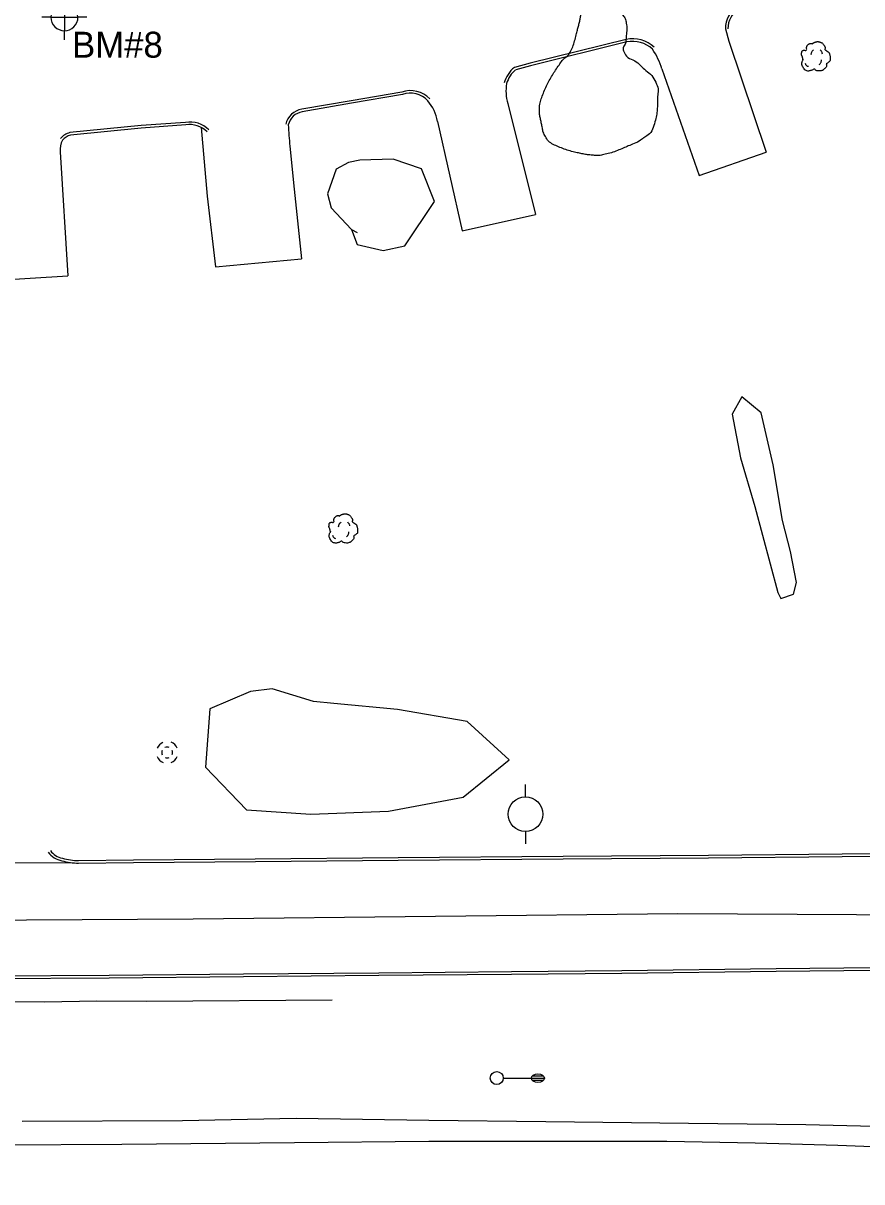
# Model space of a CAD drawing. Extents: x 2145380 to 2156929, y 139568 to 149130.
# Drawn here: x 2148643.4 to 2148837.2, y 143121.1 to 143388.8 of the extents above; entities that cross this region are included whole.
import ezdxf

# ---------------------------------------------------------------- set-up
doc = ezdxf.new("R2010")
doc.units = 0
for name, color, linetype in [('SURV_Benchmark', 7, 'Continuous'), ('SURV_Text', 7, 'Continuous'), ('TOPO_Asphalt', 7, 'Continuous'), ('TOPO_Curb Back', 7, 'Continuous'), ('TOPO_DRAIN_Manhole', 7, 'Continuous'), ('TOPO_Flowline', 7, 'Continuous'), ('TOPO_Light Pole', 7, 'Continuous'), ('TOPO_Power Pole', 7, 'Continuous'), ('TOPO_Tree', 7, 'Continuous'), ('TOPO_Tree Line', 7, 'Continuous')]:
    doc.layers.add(name, color=color, linetype=linetype)

# ---------------------------------------------------------------- blocks, each defined once
blk = doc.blocks.new('MHEXST')
at = {"layer": 'TOPO_DRAIN_Manhole'}
for centre, radius, start, end in [((-0.1, 0.3), 12.7, 112.9748, 158.2636), ((-0.1, 0.1), 6.35, 157.9722, 204.161), ((-0.1, 0.1), 6.35, 66.1941, 113.691), ((-0.1, 0.3), 12.7, 22.0744, 68.6991), ((-0.1, 0.1), 6.35, 336.8023, 21.4046), ((-0.1, 0.3), 12.7, 202.6921, 248.1938), ((-0.1, 0.1), 6.35, 248.5791, 293.1995), ((-0.1, 0.3), 12.7, 291.7963, 337.3032)]:
    blk.add_arc(centre, radius, start, end, dxfattribs=at)
blk = doc.blocks.new('LP')
at = {"layer": 'TOPO_Light Pole'}
blk.add_line((3.81, 0), (20.32, 0), dxfattribs=at)
for points in [[(20.32, 0), (27.94, 0)], [(20.32, 0), (23.5, 0)], [(20.83, 1.27), (27.43, 1.27)], [(20.83, 1.27), (23.5, 1.27)], [(23.71, 1.27), (27.43, 1.27)], [(23.71, 0), (27.94, 0)], [(20.83, -1.27), (27.43, -1.27)], [(20.83, -1.27), (23.5, -1.27)], [(23.71, -1.27), (27.43, -1.27)]]:
    blk.add_lwpolyline(points, dxfattribs=at)
blk.add_circle((0, 0), 3.81, dxfattribs=at)
blk.add_ellipse((24.13, 0), major_axis=(3.81, 0), ratio=0.666667, dxfattribs=at)
blk = doc.blocks.new('TREE')
at = {"layer": 'TOPO_Tree'}
for points in [[(-14.1, -0.4), (-14.2, 0.5), (-14.4, 1.4), (-14.6, 2.3), (-14.8, 3.2), (-15.5, 4), (-15.7, 4.9), (-15.8, 5.6), (-15.7, 6.3), (-15.7, 7), (-15.6, 7.9), (-15.7, 8.8), (-15.1, 9.7), (-14.6, 10.4), (-13.8, 10.5), (-13, 10.7), (-12.2, 11), (-11.1, 10), (-10.4, 10.7), (-9.4, 11.7), (-10.3, 13.3), (-9.8, 14.4), (-9.6, 15.1), (-9.3, 15.9), (-8.8, 16.5), (-8.2, 17.3), (-7.5, 17.7), (-6.7, 18.1), (-6.1, 18.4), (-5.6, 18.6), (-5.1, 18.7), (-4.5, 18.7), (-4, 18.5), (-3.5, 18.1)], [(-3.5, 17.6), (-3.1, 18.3), (-2.6, 18.8), (-1.9, 19.2), (-1, 19.7), (-0.2, 20), (0.7, 20.2), (1.6, 20.5), (2.5, 20.8), (3.4, 20.8), (4.1, 20.7), (4.8, 20.5), (5.5, 20.2), (6.4, 19.9), (7.3, 19.7), (8.2, 19.2), (9.4, 18.4), (10, 17.2), (10.8, 16), (11.2, 15.3), (11.6, 14.6), (11.9, 13.9), (12.2, 13.1), (11.4, 12), (11.9, 11.2), (12, 11), (12.2, 10.9), (12.4, 10.7), (12.9, 10.4), (13.5, 10), (14, 9.7), (14.7, 9.2), (15.4, 8.7), (16.1, 8.1), (16.7, 7.5), (16.9, 6.7), (17.1, 6), (17.6, 4.4), (17.7, 2.8), (17.7, 1.2), (17.7, -0.2), (17.8, -2.2), (16.6, -3), (15.5, -3.8), (14.3, -4.6), (13.2, -5.3)], [(13.2, -5.3), (13.3, -5.8), (13.4, -6.3), (13.4, -6.7), (13.8, -8.5), (12.2, -10), (10.8, -11.5), (10, -12.3), (9.1, -12.8), (8.2, -13.1), (6, -13.8), (3.3, -13.6), (1.3, -13.1), (0.5, -12.9), (-0.1, -11.4), (-0.8, -11.5), (-2, -11.6), (-3.3, -12.8), (-4.5, -13.1), (-6.1, -13.5), (-7.8, -14), (-9.3, -13.6), (-11.4, -13.1), (-12.8, -11.4), (-14.1, -9.4), (-15.3, -7.3), (-15.6, -5.1), (-15.1, -3), (-14.9, -1.9), (-13.9, -0.8), (-13.5, 0.1)], [(-4.2, 5.1), (-4.5, 6.1), (-4.3, 7.2), (-3.8, 8.2), (-3.3, 9.3), (-2.7, 10.3), (-1.6, 11)], [(5.9, 11.2), (6.5, 10.7), (7, 10.2), (7.4, 9.5), (7.9, 8.6), (8.3, 7.6), (8.5, 6.6)], [(-11.4, -4.5), (-11.5, -5.4), (-11, -6.3), (-10.1, -7.2), (-9.3, -8), (-8.5, -8.3), (-7.7, -8.1)], [(4.8, -6.3), (5.7, -5.7), (6.3, -4.9), (6.8, -3.9), (7.4, -2.8), (7.6, -1.7), (7.5, -0.6)]]:
    blk.add_open_spline(points, degree=3, dxfattribs=at)
blk = doc.blocks.new('POWPOL')
at = {"layer": 'TOPO_Power Pole'}
for p, q in [((0, 10.16), (0, 17.34)), ((0, -10.16), (0, -17.34))]:
    blk.add_line(p, q, dxfattribs=at)
blk.add_circle((0, 0), 10.16, dxfattribs=at)
blk = doc.blocks.new('BM')
at = {"layer": 'SURV_Benchmark'}
for p, q in [((0, 2.49), (0, 4.15)), ((-2.49, 0), (-4.16, 0)), ((4.16, 0), (2.49, 0)), ((0, -4.16), (0, -2.49))]:
    blk.add_line(p, q, dxfattribs=at)
for points in [[(0, 2.49), (0, 2.49), (0, 0), (2.49, 0), (2.49, 0), (2.49, 0)], [(0, 2.49), (0, 2.49), (0, 0), (2.49, 0), (2.49, 0), (2.49, 0), (2.49, 0)], [(-2.5, 0), (-2.49, 0), (0, 0), (0, -2.49), (0, -2.49)], [(-2.5, 0), (-2.49, 0), (0, 0), (0, -2.49), (0, -2.49)]]:
    blk.add_lwpolyline(points, dxfattribs=at)
for start, end in [(90.0638, 180.0068), (0.0638, 90.0068), (0.0638, 90.0068), (180.0638, 270.0068), (180.0638, 270.0068), (269.9472, 359.9927)]:
    blk.add_arc((0, 0), 2.5, start, end, dxfattribs=at)

msp = doc.modelspace()

# ---------------------------------------------------------------- linework, layer by layer
at = {"layer": 'TOPO_Asphalt'}
msp.add_line((2148638.73, 143194.83), (2148654.37, 143194.89), dxfattribs=at)
for points in [[(2148805.66, 143387.52), (2148806.45, 143384.7), (2148815.04, 143359.01)], [(2148791, 143378.26), (2148799.59, 143353.64), (2148815.04, 143359.01)], [(2148755.36, 143370.26), (2148761.79, 143344.63)], [(2148684.53, 143364.76), (2148685.95, 143348.9), (2148687.84, 143332.53), (2148707.7, 143334.38)], [(2148739.17, 143366.12), (2148744.87, 143340.82), (2148761.79, 143344.63)], [(2148652, 143359.13), (2148653.72, 143330.43)], [(2148705.04, 143360.41), (2148706.01, 143350.46), (2148707.7, 143334.38)], [(2148634.26, 143356.55), (2148636.24, 143329.37), (2148653.72, 143330.43)], [(2148216.84, 143158.69), (2148184.37, 143167.11), (2148139.58, 143177.42), (2148189.05, 143177.78), (2148318.26, 143178.67), (2148453.68, 143179.86), (2148495.97, 143180.36), (2148592.79, 143181.36), (2148682.71, 143181.88), (2148794.65, 143183.07), (2148863.49, 143182.7), (2148938.54, 143181.62), (2149047.47, 143180.42), (2149160.93, 143178.65), (2149279.68, 143176.62), (2149348.44, 143174.22)], [(2148643.21, 143135.11), (2148680.2, 143135.25), (2148706.46, 143135.78), (2148737.18, 143135.34), (2148764.16, 143135.01), (2148797.1, 143134.65), (2148824.23, 143134.35), (2148846.36, 143133.84), (2148871.54, 143133.46), (2148890.64, 143132.83), (2148924.63, 143131.18), (2148957.94, 143130.63), (2148994.98, 143130.18), (2149015.73, 143130.46), (2149052.38, 143130.49)], [(2149046.11, 143121.1), (2149021.59, 143121.99), (2148990.72, 143123.37), (2148965.59, 143124.45), (2148932.94, 143125.61), (2148896.37, 143126.95), (2148859.68, 143128.43), (2148831.65, 143129.47), (2148812.54, 143130.04), (2148792.13, 143130.45), (2148763.34, 143130.43), (2148737.13, 143130.43), (2148706.11, 143130.14), (2148666.19, 143129.75), (2148638.01, 143129.58)]]:
    msp.add_lwpolyline(points, dxfattribs=at)
for centre, radius, start, end in [((2148773.75, 143372.87), 18.07, 17.3478, 33.5372), ((2148765.76, 143373.13), 10.79, 170.7152, 195.4402), ((2148728.76, 143364.16), 10.59, 10.6512, 39.598), ((2148794.29, 143369.43), 89.7, 182.6155, 185.7738), ((2148656.79, 143359.57), 4.82, 152.614, 185.1728)]:
    msp.add_arc(centre, radius, start, end, dxfattribs=at)
at = {"layer": 'TOPO_Curb Back'}
for points in [[(2148782.73, 143385.07), (2148760.52, 143379.59), (2148756.93, 143378.61)], [(2148782.87, 143384.49), (2148760.67, 143379.01), (2148757.21, 143378.06)], [(2148730.88, 143372.91), (2148719.21, 143370.93), (2148707.81, 143368.94)], [(2148731.03, 143372.32), (2148719.31, 143370.34), (2148707.91, 143368.35)], [(2148680.94, 143365.91), (2148670.67, 143365.17), (2148654.22, 143363.55)], [(2148681.01, 143365.31), (2148670.72, 143364.57), (2148654.32, 143362.96)], [(2148656.23, 143194.73), (2148668.9, 143194.88), (2148697.06, 143195.11), (2148730.06, 143195.41), (2148768.2, 143195.74), (2148801.73, 143195.96), (2148832.61, 143196.26), (2148862.3, 143196.58), (2148888.28, 143196.76), (2148919.4, 143196.87), (2148952.65, 143197.23), (2148977.06, 143197.44), (2149014.23, 143198), (2149048.64, 143198.29)], [(2148656.24, 143195.33), (2148668.89, 143195.48), (2148697.05, 143195.71), (2148730.06, 143196.01), (2148768.2, 143196.34), (2148801.73, 143196.56), (2148832.6, 143196.86), (2148862.3, 143197.18), (2148888.27, 143197.36), (2148919.39, 143197.47), (2148952.65, 143197.83), (2148977.06, 143198.04), (2149014.23, 143198.6), (2149048.63, 143198.89)], [(2148636.21, 143168.69), (2148663.32, 143168.82), (2148694.34, 143169.18), (2148725.59, 143169.43), (2148756.22, 143169.67), (2148781.7, 143169.95), (2148817.36, 143170.41), (2148856.46, 143170.75), (2148907.3, 143171.24), (2148938.06, 143171.32), (2148971.54, 143171.7), (2149005.21, 143172.1), (2149045.87, 143172.68)], [(2148636.21, 143168.09), (2148663.32, 143168.22), (2148694.35, 143168.58), (2148725.59, 143168.83), (2148756.23, 143169.07), (2148781.71, 143169.35), (2148817.37, 143169.81), (2148856.47, 143170.15), (2148907.31, 143170.64), (2148938.06, 143170.72), (2148971.55, 143171.1), (2149005.21, 143171.5), (2149045.87, 143172.08)]]:
    msp.add_lwpolyline(points, dxfattribs=at)
for centre, radius, start, end in [((2148811.14, 143387.75), 5.49, 118.3665, 182.3324), ((2148811.14, 143387.75), 4.89, 118.8391, 182.3322), ((2148784.23, 143377.8), 7.43, 47.7189, 101.5908), ((2148784.23, 143377.8), 6.83, 47.7176, 101.4927), ((2148760.97, 143373.31), 6.66, 127.3324, 165.1275), ((2148760.97, 143373.31), 6.06, 128.417, 165.127), ((2148732.91, 143367.18), 6.08, 42.9741, 109.5874), ((2148732.91, 143367.18), 5.48, 42.9755, 110.1205), ((2148708.52, 143364.46), 4.54, 99.0318, 167.1069), ((2148708.52, 143364.46), 3.94, 98.97, 167.106), ((2148681.97, 143359.9), 6.1, 44.3201, 99.7684), ((2148681.97, 143359.9), 5.5, 44.3176, 100.0716), ((2148655.23, 143359.59), 4.09, 104.3291, 140.9991), ((2148655.23, 143359.58), 3.49, 105.0564, 140.9961), ((2148653.28, 143200.23), 5.01, 215.8038, 259.5173), ((2148653.28, 143200.23), 4.41, 215.8025, 259.8106), ((2148656.77, 143211.86), 17.14, 255.1104, 268.1859), ((2148656.77, 143211.86), 16.54, 255.0295, 268.1414)]:
    msp.add_arc(centre, radius, start, end, dxfattribs=at)
at = {"layer": 'TOPO_Flowline'}
msp.add_lwpolyline([(2148714.8, 143163.08), (2148671.92, 143162.78), (2148660.47, 143162.88), (2148648.36, 143162.65), (2148628.17, 143162.71), (2148613.26, 143161.69), (2148597.01, 143160.8), (2148586.19, 143161.84), (2148569.02, 143162.01), (2148560.16, 143160.28), (2148548.77, 143158.35), (2148525.97, 143156.47), (2148519.46, 143156.42), (2148509.69, 143155.95), (2148507.93, 143155.68), (2148507.39, 143155.72)], dxfattribs=at)
at = {"layer": 'TOPO_Tree Line'}
for points in [[(2148719.24, 143341.17), (2148720.56, 143337.71), (2148726.6, 143336.29), (2148731.62, 143337.38), (2148738.44, 143347.65), (2148735.47, 143355.19), (2148728.93, 143357.4), (2148721.21, 143357.2), (2148718.62, 143356.64), (2148715.73, 143355.13), (2148713.76, 143349.44), (2148714.55, 143346.15), (2148719.24, 143341.17), (2148720.55, 143340.48)], [(2148818.46, 143255.92), (2148821.36, 143256.86), (2148822.1, 143259.57), (2148820.71, 143266.72), (2148818.82, 143273.91), (2148816.71, 143286.75), (2148813.95, 143298.76), (2148809.45, 143302.5), (2148807.25, 143298.52), (2148809.14, 143288.4), (2148812.47, 143277.17), (2148817.76, 143257.29), (2148818.46, 143255.92)], [(2148710.52, 143232.12), (2148700.94, 143235.04), (2148695.97, 143234.44), (2148686.53, 143230.41), (2148685.56, 143216.9), (2148695.02, 143207.05), (2148709.86, 143206.05), (2148727.79, 143206.78), (2148745.06, 143210), (2148755.71, 143218.61), (2148745.97, 143227.48), (2148729.87, 143230.25), (2148715.21, 143231.66), (2148710.52, 143232.12)]]:
    msp.add_lwpolyline(points, dxfattribs=at)
msp.add_open_spline([(2148785.32, 143361.34), (2148785.93, 143361.74), (2148786.53, 143362.14), (2148787.14, 143362.54), (2148788.51, 143363.46), (2148789.19, 143365.2), (2148789.58, 143366.84), (2148789.9, 143368.17), (2148789.94, 143369.5), (2148789.97, 143370.84), (2148790, 143372.26), (2148790.27, 143373.69), (2148789.6, 143375.11), (2148788.76, 143376.89), (2148787.27, 143377.84), (2148786.01, 143379.1), (2148784.84, 143380.26), (2148782.92, 143380.74), (2148782.2, 143382.3), (2148781.83, 143383.11), (2148782.61, 143384), (2148782.67, 143384.87), (2148782.77, 143386.31), (2148782.99, 143387.77), (2148782.68, 143389.2), (2148782.48, 143390.13), (2148781.84, 143390.83), (2148781.09, 143391.51), (2148779.9, 143392.61), (2148778.62, 143393.22), (2148777.26, 143393.86), (2148776.27, 143394.33), (2148774.96, 143394.92), (2148774.03, 143394.27), (2148773.21, 143393.71), (2148772.71, 143392.8), (2148772.49, 143391.87), (2148772.3, 143391.03), (2148772.2, 143390.18), (2148772, 143389.34), (2148771.77, 143388.39), (2148771.53, 143387.44), (2148771.28, 143386.49), (2148770.92, 143385.09), (2148770.56, 143383.7), (2148769.92, 143382.39), (2148769.39, 143381.32), (2148768.28, 143380.69), (2148767.62, 143379.73), (2148766.82, 143378.58), (2148766.05, 143377.42), (2148765.34, 143376.19), (2148764.61, 143374.94), (2148764.01, 143373.71), (2148763.46, 143372.31), (2148762.97, 143371.05), (2148762.67, 143369.77), (2148762.71, 143368.49), (2148762.74, 143367.53), (2148762.96, 143366.56), (2148763.17, 143365.6), (2148763.38, 143364.6), (2148763.53, 143363.62), (2148764.05, 143362.68), (2148764.7, 143361.49), (2148765.87, 143360.79), (2148767.08, 143360.28), (2148768.43, 143359.72), (2148769.77, 143359.29), (2148771.18, 143358.96), (2148772.24, 143358.72), (2148773.3, 143358.51), (2148774.37, 143358.39), (2148775.41, 143358.27), (2148776.48, 143358.21), (2148777.51, 143358.45), (2148778.96, 143358.78), (2148780.37, 143359.25), (2148781.74, 143359.83), (2148782.93, 143360.33), (2148784.13, 143360.83), (2148785.32, 143361.34), (2148785.32, 143361.34)], degree=3, dxfattribs=at)

# ---------------------------------------------------------------- block references
at = {"layer": 'SURV_Benchmark', "xscale": 1.25, "yscale": 1.25}
msp.add_blockref('BM', (2148652.95, 143390.22), dxfattribs=at)
at = {"layer": 'TOPO_DRAIN_Manhole', "xscale": 0.19685000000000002, "yscale": 0.19685000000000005}
msp.add_blockref('MHEXST', (2148676.7, 143220.29), dxfattribs=at)
at = {"layer": 'TOPO_Light Pole', "xscale": 0.39370000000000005, "yscale": 0.3937000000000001}
msp.add_blockref('LP', (2148752.84, 143145.08), dxfattribs=at)
at = {"layer": 'TOPO_Power Pole', "xscale": 0.39370000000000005, "yscale": 0.3937000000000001}
msp.add_blockref('POWPOL', (2148759.46, 143206.06), dxfattribs=at)
at = {"layer": 'TOPO_Tree', "xscale": 0.19685000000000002, "yscale": 0.19685000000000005}
for p in [(2148826.36, 143380.49), (2148717.17, 143271.4)]:
    msp.add_blockref('TREE', p, dxfattribs=at)

# ---------------------------------------------------------------- texts
at = {"layer": 'SURV_Text'}
msp.add_text('BM#8', height=6, dxfattribs=at).set_placement((2148654.72, 143380.86))

doc.saveas('drawing.dxf')
